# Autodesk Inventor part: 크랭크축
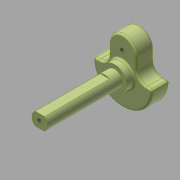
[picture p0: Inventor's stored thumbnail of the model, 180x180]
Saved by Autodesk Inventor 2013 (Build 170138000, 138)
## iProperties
Created: 2018-01
Part Number: 크랭크축
Material: 강철, 탄소
Document SubType Name: Modeling
Designer: mduedu
Density: 7.87 g/cm^3
Mass: 57.3413 g
Surface Area: 32.1344 cm^2
Volume: 7.28606 cm^3
Author: mduedu
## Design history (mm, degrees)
sketch "스케치1"
  geometry: L1 (-15, 0)-(15, 0); L2 (-7, 0)-(7, 0); L3 (7, 0)-(7, 10); L4 (-7, 10)-(-7, 0); A1 r 15 centre (0, 0) between (-15, 0) and (15, 0); A2 r 7 centre (0, 10) between (7, 10) and (-7, 10); 3 further points
  constraints: 8 end point, 4 point on circle, 3 coincident, 2 centre point, 2 horizontal, 2 midpoint, 2 tangent, 1 parallel, 1 perpendicular, 1 point on line
  dimensions: "d0" = 30 diameter of A1; "d1" = 17 dimension on A2 L1; "d2" = 7 radius of A2
extrude "돌출1" new body sketch "스케치1" distance "d4" = 9; taper "d5" = 0 deg
sketch "스케치2"
  geometry: C1 r 6 at (0, 0); 1 further point
  constraints: 1 centre point, 1 coincident
  dimensions: "d6" = 12 diameter of C1
extrude "돌출2" join sketch "스케치2" distance "d7" = 4; taper "d8" = 0 deg
sketch "스케치3"
  geometry: C1 r 4 at (0, 0); 1 further point
  constraints: 1 centre point, 1 coincident
  dimensions: "d9" = 8 diameter of C1
extrude "돌출3" join sketch "스케치3" distance "d10" = 38; taper "d11" = 0 deg
sketch "스케치4"
  geometry: L1 (-2.332, 3.25)-(2.332, 3.25); L2 (-2.332, -3.25)-(2.332, -3.25); A1 r 4 centre (0, 0) between (-2.332, 3.25) and (2.332, 3.25) reference; A2 r 4 centre (0, 0) between (2.332, 3.25) and (-2.332, 3.25); A3 r 4 centre (0, 0) between (-2.332, -3.25) and (2.332, -3.25); 1 further point
  constraints: 8 point on circle, 4 end point, 2 centre point, 2 coincident, 2 parallel, 1 horizontal
  dimensions: "d12" = 6.5 distance between parallel lines of L2 L1
extrude "돌출4" cut sketch "스케치4" distance "d13" = 33; taper "d14" = 0 deg
fillet "모깎기1" dims "d15" = 5
fillet "모깎기2" dims "d16" = 1
fillet "모깎기3" dims "d17" = 1
fillet "모깎기4" dims "d18" = 1
sketch "스케치5"
  geometry: 1 further point
  constraints: 1 other
hole "구멍1" sketch "스케치5" at (0, 10) diameter "d19" = 2.459; stored, may be unused: countersink angle "d23" = 90 deg, drill point angle "d25" = 120 deg; dims "d20" = 10, "d21" = 4, "d22" = 2, "d24" = 11.5
sketch "스케치6"
  geometry: 1 further point
  constraints: 1 other
hole "구멍2" sketch "스케치6" at (0, 0) diameter "d26" = 2.459; stored, may be unused: countersink angle "d30" = 90 deg, drill point angle "d32" = 120 deg; dims "d27" = 12.7, "d28" = 4, "d29" = 2, "d31" = 14.2
node "솔리드1"
node "투영된 루프1"
